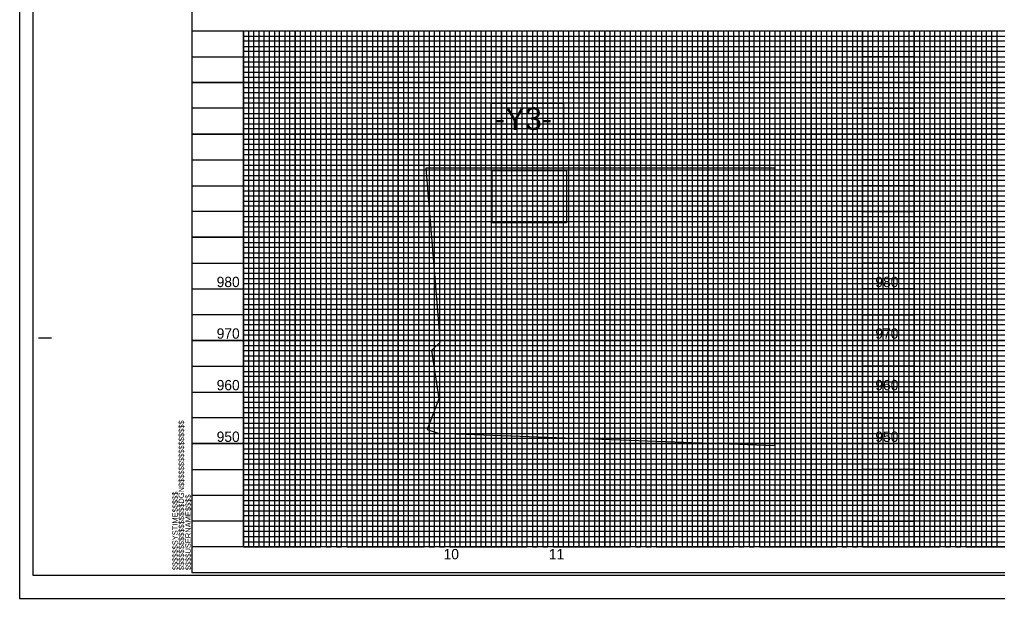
# Model space of a CAD drawing. Extents: x 1624665 to 1626605, y 896887 to 897987.
# Drawn here: x 1624665 to 1625613, y 896887 to 897448 of the extents above; entities that cross this region are included whole.
import ezdxf

# ---------------------------------------------------------------- set-up
doc = ezdxf.new("R2010")
doc.units = 0
for name, color, linetype in [('Prop DSN Text', 7, 'Continuous'), ('Prop PHM Black Shape', 7, 'Continuous'), ('Scratch_Level_1', 7, 'Continuous'), ('Sheet Cutting Line CELL', 7, 'Continuous'), ('Sheet DOT Grid CELL', 7, 'Continuous'), ('Sheet Layout Profile Border Port 2', 7, 'Continuous'), ('Sheet Plot Border Inside CELL', 7, 'Continuous'), ('Sheet Plot Border Outside CELL', 7, 'Continuous'), ('Sheet Profile CELL', 7, 'Continuous'), ('Sheet Profile Grid Major CELL', 7, 'Continuous'), ('Sheet Profile Grid Middle CELL', 7, 'Continuous'), ('Sheet Profile Grid Minor CELL', 7, 'Continuous')]:
    doc.layers.add(name, color=color, linetype=linetype)

msp = doc.modelspace()

# ---------------------------------------------------------------- linework, layer by layer
at = {"layer": 'Prop DSN Text'}
msp.add_lwpolyline([(1625122.4, 897367.44), (1625192.4, 897367.44), (1625192.4, 897337.44), (1625122.4, 897337.44)], close=True, dxfattribs=at)
at = {"layer": 'Prop PHM Black Shape'}
for points in [[(1625482.4, 897437.44), (1625532.4, 897437.44), (1625532.4, 897412.44), (1625482.4, 897412.44)], [(1625482.4, 897412.44), (1625532.4, 897412.44), (1625532.4, 897387.44), (1625482.4, 897387.44)], [(1625482.4, 897387.44), (1625532.4, 897387.44), (1625532.4, 897362.44), (1625482.4, 897362.44)], [(1625122.4, 897367.44), (1625192.4, 897367.44), (1625192.4, 897337.44), (1625122.4, 897337.44)], [(1625482.4, 897362.44), (1625532.4, 897362.44), (1625532.4, 897337.44), (1625482.4, 897337.44)], [(1625482.4, 897337.44), (1625532.4, 897337.44), (1625532.4, 897312.44), (1625482.4, 897312.44)], [(1625482.4, 897312.44), (1625532.4, 897312.44), (1625532.4, 897287.44), (1625482.4, 897287.44)], [(1625123.29, 897302.04), (1625195.25, 897302.04), (1625195.25, 897251.3), (1625123.29, 897251.3)], [(1625482.4, 897287.44), (1625532.4, 897287.44), (1625532.4, 897262.44), (1625482.4, 897262.44)], [(1625482.4, 897262.44), (1625532.4, 897262.44), (1625532.4, 897237.44), (1625482.4, 897237.44)], [(1625482.4, 897237.44), (1625532.4, 897237.44), (1625532.4, 897212.44), (1625482.4, 897212.44)], [(1625482.4, 897212.44), (1625532.4, 897212.44), (1625532.4, 897187.44), (1625482.4, 897187.44)], [(1625482.4, 897187.44), (1625532.4, 897187.44), (1625532.4, 897162.44), (1625482.4, 897162.44)], [(1625482.4, 897162.44), (1625532.4, 897162.44), (1625532.4, 897137.44), (1625482.4, 897137.44)], [(1625482.4, 897137.44), (1625532.4, 897137.44), (1625532.4, 897112.44), (1625482.4, 897112.44)], [(1625482.4, 897112.44), (1625532.4, 897112.44), (1625532.4, 897087.44), (1625482.4, 897087.44)], [(1625482.4, 897087.44), (1625532.4, 897087.44), (1625532.4, 897062.44), (1625482.4, 897062.44)], [(1625482.4, 897062.44), (1625532.4, 897062.44), (1625532.4, 897037.44), (1625482.4, 897037.44)], [(1625482.4, 897037.44), (1625532.4, 897037.44), (1625532.4, 897012.44), (1625482.4, 897012.44)], [(1625482.4, 897012.44), (1625532.4, 897012.44), (1625532.4, 896987.44), (1625482.4, 896987.44)], [(1625482.4, 896987.44), (1625532.4, 896987.44), (1625532.4, 896962.44), (1625482.4, 896962.44)], [(1625482.4, 896962.44), (1625532.4, 896962.44), (1625532.4, 896937.44), (1625482.4, 896937.44)]]:
    msp.add_lwpolyline(points, close=True, dxfattribs=at)
at = {"layer": 'Scratch_Level_1'}
msp.add_lwpolyline([(1625072.01, 897146.43), (1625072.69, 897135.35), (1625064.6, 897127.75), (1625071.58, 897080.87), (1625060.24, 897051.13), (1625071.02, 897047.47), (1625397.25, 897035.69), (1625397.25, 897304.35), (1625059.02, 897304.35)], close=True, dxfattribs=at)
at = {"layer": 'Sheet Cutting Line CELL'}
for p, q in [((1624665.4, 897987.44), (1624665.4, 896887.44)), ((1624665.4, 896887.44), (1626349.4, 896887.44))]:
    msp.add_line(p, q, dxfattribs=at)
at = {"layer": 'Sheet DOT Grid CELL'}
for p, q in [((1624832.4, 897437.44), (1626332.29, 897437.44)), ((1624882.4, 897437.44), (1624882.4, 896937.44)), ((1624932.4, 897437.44), (1624932.4, 896937.44)), ((1624982.4, 897437.44), (1624982.4, 896937.44)), ((1625032.4, 897437.44), (1625032.4, 896937.44)), ((1625082.4, 897437.44), (1625082.4, 896937.44)), ((1625132.4, 897437.44), (1625132.4, 896937.44)), ((1625182.4, 897437.44), (1625182.4, 896937.44)), ((1625232.4, 897437.44), (1625232.4, 896937.44)), ((1625282.4, 897437.44), (1625282.4, 896937.44)), ((1625332.4, 897437.44), (1625332.4, 896937.44)), ((1625382.4, 897437.44), (1625382.4, 896937.44)), ((1625432.4, 897437.44), (1625432.4, 896937.44)), ((1625482.4, 897437.44), (1625482.4, 896937.44)), ((1625532.4, 897437.44), (1625532.4, 896937.44)), ((1625582.4, 897437.44), (1625582.4, 896937.44)), ((1624832.4, 897387.44), (1626332.29, 897387.44)), ((1624832.4, 897337.44), (1626332.29, 897337.44)), ((1624832.4, 897287.44), (1626332.29, 897287.44)), ((1624832.4, 897237.44), (1626332.29, 897237.44)), ((1624832.4, 897187.44), (1626332.29, 897187.44)), ((1624832.4, 897137.44), (1626332.29, 897137.44)), ((1624832.4, 897087.44), (1626332.29, 897087.44)), ((1624832.4, 897037.44), (1626332.29, 897037.44)), ((1624832.4, 896987.44), (1626332.29, 896987.44))]:
    msp.add_line(p, q, dxfattribs=at)
at = {"layer": 'Sheet Layout Profile Border Port 2'}
msp.add_lwpolyline([(1624882.4, 897437.44), (1626282.4, 897437.44), (1626282.4, 896937.44), (1624882.4, 896937.44)], close=True, dxfattribs=at)
at = {"layer": 'Sheet Plot Border Inside CELL'}
msp.add_lwpolyline([(1624678.4, 896909.89), (1626344.9, 896909.89), (1626344.9, 897964.99), (1624678.4, 897964.99)], close=True, dxfattribs=at)
at = {"layer": 'Sheet Plot Border Outside CELL'}
msp.add_lwpolyline([(1624665.4, 896887.44), (1626349.4, 896887.44), (1626349.4, 897987.44), (1624665.4, 897987.44)], close=True, dxfattribs=at)
at = {"layer": 'Sheet Profile CELL'}
for p, q in [((1624832.4, 897437.44), (1626332.4, 897437.44)), ((1624683.9, 897139.94), (1624696.4, 897139.94)), ((1626332.4, 896937.44), (1624832.4, 896937.44)), ((1624832.4, 896912.44), (1626332.4, 896912.44)), ((1624832.4, 896912.44), (1624832.4, 896912.44)), ((1624832.4, 896912.44), (1624832.4, 896912.44)), ((1624832.4, 896912.44), (1624832.4, 896912.44)), ((1624832.4, 896912.44), (1624832.4, 896912.44)), ((1624832.4, 896912.44), (1624832.4, 896912.44)), ((1624832.4, 896912.44), (1624832.4, 896912.44)), ((1624832.4, 896912.44), (1624832.4, 896912.44))]:
    msp.add_line(p, q, dxfattribs=at)
msp.add_lwpolyline([(1626332.4, 897962.44), (1624832.4, 897962.44), (1624832.4, 896912.44), (1626332.4, 896912.44)], close=True, dxfattribs=at)
msp.add_lwpolyline([(1624869.9, 896912.44), (1624869.9, 896912.44)], dxfattribs=at)
at = {"layer": 'Sheet Profile Grid Major CELL'}
for p, q in [((1625332.4, 897437.44), (1625382.4, 897437.44)), ((1625432.4, 897437.44), (1625482.4, 897437.44)), ((1625532.4, 897437.44), (1625582.4, 897437.44)), ((1625482.4, 897412.44), (1625532.4, 897412.44)), ((1625482.4, 897387.44), (1625532.4, 897387.44)), ((1625532.4, 897362.44), (1625482.4, 897362.44)), ((1625482.4, 897337.44), (1625532.4, 897337.44)), ((1625482.4, 897312.44), (1625532.4, 897312.44)), ((1625482.4, 897287.44), (1625532.4, 897287.44)), ((1625482.4, 897262.44), (1625532.4, 897262.44)), ((1625482.4, 897237.44), (1625532.4, 897237.44)), ((1625482.4, 897212.44), (1625532.4, 897212.44)), ((1625482.4, 897187.44), (1625532.4, 897187.44)), ((1625482.4, 897162.44), (1625532.4, 897162.44)), ((1625482.4, 897137.44), (1625532.4, 897137.44)), ((1625482.4, 897112.44), (1625532.4, 897112.44)), ((1625482.4, 897087.44), (1625532.4, 897087.44)), ((1625482.4, 897062.44), (1625532.4, 897062.44)), ((1625482.4, 897037.44), (1625532.4, 897037.44)), ((1625482.4, 897012.44), (1625532.4, 897012.44)), ((1625482.4, 896987.44), (1625532.4, 896987.44)), ((1625482.4, 896962.44), (1625532.4, 896962.44)), ((1624832.4, 896937.44), (1624832.4, 896937.44))]:
    msp.add_line(p, q, dxfattribs=at)
for points in [[(1624882.4, 897437.44), (1624882.4, 896937.44), (1624932.4, 896937.44), (1624932.4, 897437.44), (1624982.4, 897437.44), (1624982.4, 896937.44), (1625032.4, 896937.44), (1625032.4, 897437.44), (1625082.4, 897437.44), (1625082.4, 896937.44), (1625132.4, 896937.44), (1625132.4, 897437.44), (1625182.4, 897437.44), (1625182.4, 896937.44), (1625232.4, 896937.44), (1625232.4, 897437.44), (1625282.4, 897437.44), (1625282.4, 896937.44), (1625332.4, 896937.44), (1625332.4, 897437.44), (1625382.4, 897437.44), (1625382.4, 896937.44), (1625432.4, 896937.44), (1625432.4, 897437.44), (1625482.4, 897437.44), (1625482.4, 896937.44), (1625532.4, 896937.44), (1625532.4, 897437.44), (1625582.4, 897437.44), (1625582.4, 896937.44), (1625632.4, 896937.44)], [(1626332.4, 897387.44), (1624832.4, 897387.44)], [(1626332.4, 897337.44), (1624832.4, 897337.44), (1624832.4, 897287.44), (1626332.4, 897287.44)], [(1626332.4, 897237.44), (1624832.4, 897237.44), (1624832.4, 897187.44), (1626332.4, 897187.44)], [(1626332.4, 897137.44), (1624832.4, 897137.44), (1624832.4, 897087.44), (1626332.4, 897087.44)], [(1626332.4, 897037.44), (1624832.4, 897037.44), (1624832.4, 897037.44), (1624832.4, 896987.44), (1626332.4, 896987.44)], [(1626332.4, 896937.44), (1624832.4, 896937.44)]]:
    msp.add_lwpolyline(points, dxfattribs=at)
at = {"layer": 'Sheet Profile Grid Middle CELL'}
for points in [[(1624857.4, 897437.44), (1624907.4, 897437.44), (1624907.4, 896937.44), (1624957.4, 896937.44), (1624957.4, 897437.44), (1625007.4, 897437.44), (1625007.4, 896937.44), (1625057.4, 896937.44), (1625057.4, 897437.44), (1625107.4, 897437.44), (1625107.4, 896937.44), (1625157.4, 896937.44), (1625157.4, 897437.44), (1625207.4, 897437.44), (1625207.4, 896937.44), (1625257.4, 896937.44), (1625257.4, 897437.44), (1625307.4, 897437.44), (1625307.4, 896937.44), (1625357.4, 896937.44), (1625357.4, 897437.44), (1625407.4, 897437.44), (1625407.4, 896937.44), (1625457.4, 896937.44), (1625457.4, 896937.44), (1625457.4, 897437.44), (1625507.4, 897437.44), (1625507.4, 896937.44), (1625557.4, 896937.44), (1625557.4, 897437.44), (1625607.4, 897437.44), (1625607.4, 896937.44), (1625657.4, 896937.44)], [(1624832.4, 897412.44), (1626332.4, 897412.44)], [(1626332.4, 897362.44), (1624832.4, 897362.44), (1624832.4, 897312.44), (1626332.4, 897312.44)], [(1626332.4, 897262.44), (1624832.4, 897262.44), (1624832.4, 897212.44), (1626332.4, 897212.44)], [(1626332.4, 897162.44), (1624832.4, 897162.44), (1624832.4, 897112.44), (1626332.4, 897112.44)], [(1626332.4, 897062.44), (1624832.4, 897062.44), (1624832.4, 897012.44), (1626332.4, 897012.44)], [(1626332.4, 896962.44), (1624832.4, 896962.44)]]:
    msp.add_lwpolyline(points, dxfattribs=at)
at = {"layer": 'Sheet Profile Grid Minor CELL'}
for p, q in [((1624882.4, 897432.44), (1626282.4, 897432.44)), ((1626282.4, 897427.44), (1624882.4, 897427.44)), ((1624882.4, 897422.44), (1626282.4, 897422.44)), ((1626282.4, 897417.44), (1624882.4, 897417.44)), ((1624882.4, 897407.44), (1626282.4, 897407.44)), ((1626282.4, 897402.44), (1624882.4, 897402.44)), ((1624882.4, 897397.44), (1626282.4, 897397.44)), ((1626282.4, 897392.44), (1624882.4, 897392.44)), ((1624882.4, 897382.44), (1626282.4, 897382.44)), ((1626282.4, 897377.44), (1624882.4, 897377.44)), ((1624882.4, 897372.44), (1626282.4, 897372.44)), ((1626282.4, 897367.44), (1624882.4, 897367.44)), ((1624882.4, 897357.44), (1626282.4, 897357.44)), ((1626282.4, 897352.44), (1624882.4, 897352.44)), ((1624882.4, 897347.44), (1626282.4, 897347.44)), ((1626282.4, 897342.44), (1624882.4, 897342.44)), ((1624882.4, 897332.44), (1626282.4, 897332.44)), ((1626282.4, 897327.44), (1624882.4, 897327.44)), ((1624882.4, 897322.44), (1626282.4, 897322.44)), ((1626282.4, 897317.44), (1624882.4, 897317.44)), ((1624882.4, 897307.44), (1626282.4, 897307.44)), ((1626282.4, 897302.44), (1624882.4, 897302.44)), ((1624882.4, 897297.44), (1626282.4, 897297.44)), ((1626282.4, 897292.44), (1624882.4, 897292.44)), ((1624882.4, 897282.44), (1626282.4, 897282.44)), ((1626282.4, 897277.44), (1624882.4, 897277.44)), ((1624882.4, 897272.44), (1626282.4, 897272.44)), ((1626282.4, 897267.44), (1624882.4, 897267.44)), ((1624882.4, 897257.44), (1626282.4, 897257.44)), ((1626282.4, 897252.44), (1624882.4, 897252.44)), ((1624882.4, 897247.44), (1626282.4, 897247.44)), ((1626282.4, 897242.44), (1624882.4, 897242.59)), ((1624882.4, 897232.44), (1626282.4, 897232.44)), ((1626282.4, 897227.44), (1624882.4, 897227.44)), ((1624882.4, 897222.44), (1626282.4, 897222.44)), ((1626282.4, 897217.44), (1624882.4, 897217.44)), ((1624882.4, 897207.44), (1626282.4, 897207.44)), ((1626282.4, 897202.44), (1624882.4, 897202.44)), ((1624882.4, 897197.44), (1626282.4, 897197.44)), ((1626282.4, 897192.44), (1624882.4, 897192.44)), ((1624882.4, 897182.44), (1626282.4, 897182.44)), ((1626282.4, 897177.44), (1624882.4, 897177.44)), ((1624882.4, 897172.44), (1626282.4, 897172.44)), ((1626282.4, 897167.44), (1624882.4, 897167.44)), ((1624882.4, 897157.44), (1626282.4, 897157.44)), ((1626282.4, 897152.44), (1624882.4, 897152.44)), ((1624882.4, 897147.44), (1626282.4, 897147.44)), ((1626282.4, 897142.44), (1624882.4, 897142.44)), ((1624882.4, 897132.44), (1626282.4, 897132.44)), ((1626282.4, 897127.44), (1624882.4, 897127.44)), ((1624882.4, 897122.44), (1626282.4, 897122.44)), ((1626282.4, 897117.44), (1624882.4, 897117.44)), ((1624882.4, 897107.44), (1626282.4, 897107.44)), ((1626282.4, 897102.44), (1624882.4, 897102.44)), ((1624882.4, 897097.44), (1626282.4, 897097.44)), ((1626282.4, 897092.44), (1624882.4, 897092.44)), ((1624882.4, 897082.44), (1626282.4, 897082.44)), ((1626282.4, 897077.44), (1624882.4, 897077.44)), ((1624882.4, 897072.44), (1626282.4, 897072.44)), ((1626282.4, 897067.44), (1624882.4, 897067.44)), ((1624882.4, 897057.44), (1626282.4, 897057.44)), ((1626282.4, 897052.44), (1624882.4, 897052.44)), ((1624882.4, 897047.44), (1626282.4, 897047.44)), ((1626282.4, 897042.44), (1624882.4, 897042.44)), ((1624882.4, 897032.44), (1626282.4, 897032.44)), ((1626282.4, 897027.44), (1624882.4, 897027.44)), ((1624882.4, 897022.44), (1626282.4, 897022.44)), ((1626282.4, 897017.44), (1624882.4, 897017.44)), ((1624882.4, 897007.44), (1626282.4, 897007.44)), ((1626282.4, 897002.44), (1624882.4, 897002.44)), ((1624882.4, 896997.44), (1626282.4, 896997.44)), ((1626282.4, 896992.44), (1624882.4, 896992.44)), ((1624882.4, 896982.44), (1626282.4, 896982.44)), ((1626282.4, 896977.44), (1624882.4, 896977.44)), ((1624882.4, 896972.44), (1626282.4, 896972.44)), ((1626282.4, 896967.44), (1624882.4, 896967.44)), ((1624882.4, 896957.44), (1626282.4, 896957.44)), ((1626282.4, 896952.44), (1624882.4, 896952.44)), ((1624882.4, 896947.44), (1626282.4, 896947.44)), ((1624882.4, 896942.44), (1626282.4, 896942.44))]:
    msp.add_line(p, q, dxfattribs=at)
for points in [[(1624882.4, 897437.44), (1624887.4, 897437.44), (1624887.4, 896937.44), (1624892.4, 896937.44), (1624892.4, 897437.44), (1624897.4, 897437.44), (1624897.4, 896937.44), (1624902.4, 896937.44), (1624902.4, 897437.44), (1624912.4, 897437.44), (1624912.4, 896937.44), (1624917.4, 896937.44), (1624917.4, 897437.44), (1624922.4, 897437.44), (1624922.4, 896937.44), (1624927.4, 896937.44), (1624937.4, 896937.44), (1624942.4, 896937.44), (1624942.4, 897437.44), (1624947.4, 897437.44), (1624947.4, 896937.44), (1624952.4, 896937.44), (1624952.4, 897437.44), (1624962.4, 897437.44), (1624962.4, 896937.44), (1624967.4, 896937.44), (1624967.4, 897437.44), (1624972.4, 897437.44), (1624972.4, 896937.44), (1624977.4, 896937.44), (1624977.4, 897437.44), (1624987.4, 897437.44), (1624987.4, 896937.44), (1624992.4, 896937.44), (1624992.4, 897437.44), (1624997.4, 897437.44), (1624997.4, 896937.44), (1625002.4, 896937.44), (1625002.4, 897437.44), (1625012.4, 897437.44), (1625012.4, 896937.44), (1625017.4, 896937.44), (1625017.4, 897437.44), (1625022.4, 897437.44), (1625022.4, 896937.44), (1625027.4, 896937.44), (1625027.4, 897437.44), (1625037.4, 897437.44), (1625037.4, 896937.44), (1625042.4, 896937.44), (1625042.4, 897437.44), (1625047.4, 897437.44), (1625047.4, 896937.44), (1625052.4, 896937.44), (1625052.4, 897437.44), (1625062.4, 897437.44), (1625062.4, 896937.44), (1625067.4, 896937.44), (1625067.4, 897437.44), (1625072.4, 897437.44), (1625072.4, 896937.44), (1625077.4, 896937.44), (1625077.4, 897437.44), (1625087.4, 897437.44), (1625087.4, 896937.44), (1625092.4, 896937.44), (1625092.4, 897437.44), (1625097.4, 897437.44), (1625097.4, 896937.44)], [(1624927.4, 896937.44), (1624927.4, 897437.44), (1624937.4, 897437.44), (1624937.4, 896937.44)], [(1625097.4, 896937.44), (1625102.4, 896937.44), (1625102.4, 897437.44), (1625112.4, 897437.44), (1625112.4, 896937.44), (1625117.4, 896937.44), (1625117.4, 897437.44), (1625122.4, 897437.44), (1625122.4, 896937.44), (1625127.4, 896937.44), (1625127.4, 897437.44), (1625137.4, 897437.44), (1625137.4, 896937.44), (1625142.4, 896937.44), (1625142.4, 897437.44), (1625147.4, 897437.44), (1625147.4, 896937.44), (1625152.4, 896937.44), (1625152.4, 897437.44), (1625162.4, 897437.44), (1625162.4, 896937.44), (1625167.4, 896937.44), (1625167.4, 897437.44), (1625172.4, 897437.44), (1625172.4, 896937.44), (1625177.4, 896937.44), (1625177.4, 897437.44), (1625187.4, 897437.44), (1625187.4, 896937.44), (1625192.4, 896937.44), (1625192.4, 897437.44), (1625197.4, 897437.44), (1625197.4, 896937.44), (1625202.4, 896937.44), (1625202.4, 897437.44), (1625212.4, 897437.44), (1625212.4, 896937.44), (1625217.4, 896937.44), (1625217.4, 897437.44), (1625222.4, 897437.44), (1625222.4, 896937.44), (1625227.4, 896937.44), (1625227.4, 897437.44), (1625237.4, 897437.44), (1625237.4, 896937.44), (1625242.4, 896937.44), (1625242.4, 897437.44), (1625247.4, 897437.44), (1625247.4, 896937.44), (1625252.4, 896937.44), (1625252.4, 897437.44), (1625262.4, 897437.44), (1625262.4, 896937.44), (1625267.4, 896937.44), (1625267.4, 897437.44), (1625272.4, 897437.44), (1625272.4, 896937.44), (1625277.4, 896937.44), (1625277.4, 897437.44), (1625287.4, 897437.44), (1625287.4, 896937.44), (1625292.4, 896937.44), (1625292.4, 897437.44), (1625297.4, 897437.44), (1625297.4, 896937.44), (1625302.4, 896937.44), (1625302.4, 897437.44), (1625312.4, 897437.44), (1625312.4, 896937.44), (1625317.4, 896937.44), (1625317.4, 897437.44), (1625322.4, 897437.44), (1625322.4, 896937.44), (1625327.4, 896937.44), (1625327.4, 897437.44), (1625337.4, 897437.44), (1625337.4, 896937.44), (1625342.4, 896937.44), (1625342.4, 897437.44), (1625347.4, 897437.44), (1625347.4, 896937.44), (1625352.4, 896937.44), (1625352.4, 897437.44), (1625362.4, 897437.44), (1625362.4, 896937.44), (1625367.4, 896937.44), (1625367.4, 897437.44), (1625372.4, 897437.44), (1625372.4, 896937.44), (1625377.4, 896937.44), (1625377.4, 897437.44), (1625387.4, 897437.44), (1625387.4, 896937.44), (1625392.4, 896937.44), (1625392.4, 897437.44), (1625397.4, 897437.44), (1625397.4, 896937.44), (1625402.4, 896937.44), (1625402.4, 897437.44), (1625412.4, 897437.44)], [(1625412.4, 897437.44), (1625412.4, 896937.44), (1625417.4, 896937.44), (1625417.4, 897437.44), (1625422.4, 897437.44), (1625422.4, 896937.44), (1625427.4, 896937.44), (1625427.4, 897437.44), (1625437.4, 897437.44), (1625437.4, 896937.44), (1625442.4, 896937.44), (1625442.4, 897437.44), (1625447.4, 897437.44), (1625447.4, 896937.44), (1625452.4, 896937.44), (1625452.4, 897437.44), (1625462.4, 897437.44), (1625462.4, 896937.44), (1625467.4, 896937.44), (1625467.4, 897437.44), (1625472.4, 897437.44), (1625472.4, 896937.44), (1625477.4, 896937.44), (1625477.4, 897437.44), (1625487.4, 897437.44), (1625487.4, 896937.44), (1625492.4, 896937.44), (1625492.4, 897437.44), (1625497.4, 897437.44), (1625497.4, 896937.44), (1625502.4, 896937.44), (1625502.4, 897437.44), (1625512.4, 897437.44), (1625512.4, 896937.44), (1625517.4, 896937.44), (1625517.4, 897437.44), (1625522.4, 897437.44), (1625522.4, 896937.44), (1625527.4, 896937.44), (1625527.4, 897437.44), (1625537.4, 897437.44), (1625537.4, 896937.44), (1625537.4, 896937.44), (1625542.4, 896937.44), (1625542.4, 897437.44), (1625547.4, 897437.44), (1625547.4, 896937.44), (1625552.4, 896937.44), (1625552.4, 897437.44), (1625562.4, 897437.44), (1625562.4, 896937.44), (1625567.4, 896937.44), (1625567.4, 897437.44), (1625572.4, 897437.44), (1625572.4, 896937.44), (1625577.4, 896937.44), (1625577.4, 897437.44), (1625587.4, 897437.44), (1625587.4, 896937.44), (1625592.4, 896937.44), (1625592.4, 897437.44), (1625597.4, 897437.44), (1625597.4, 896937.44), (1625602.4, 896937.44), (1625602.4, 897437.44), (1625612.4, 897437.44), (1625612.4, 896937.44), (1625617.4, 896937.44)]]:
    msp.add_lwpolyline(points, dxfattribs=at)

# ---------------------------------------------------------------- texts
at = {"layer": 'Prop DSN Text'}
for s, height, p in [('-Y3-', 21.875, (1625125.95, 897341.5)), ('980', 10, (1624856.41, 897189.17)), ('980', 10, (1625494.68, 897189.17)), ('970', 10, (1624856.41, 897139.17)), ('970', 10, (1625494.68, 897139.17)), ('960', 10, (1624856.41, 897089.17)), ('960', 10, (1625494.68, 897089.17)), ('950', 10, (1624856.41, 897039.17)), ('950', 10, (1625494.68, 897039.17)), ('10', 10, (1625076.31, 896925.38)), ('11', 10, (1625178.28, 896925.38))]:
    msp.add_text(s, height=height, dxfattribs=at).set_placement(p)
at = {"layer": 'Sheet Profile CELL'}
for s, p in [('$$$$$$$$$$$$$$$$DGN$$$$$$$$$$$$$$$$', (1624824.76, 896914.82)), ('$$$$$$SYSTIME$$$$$', (1624818.71, 896914.82)), ('$$$$USERNAME$$$$', (1624831.34, 896914.83))]:
    msp.add_text(s, height=5.25, rotation=90, dxfattribs=at).set_placement(p)

doc.saveas('drawing.dxf')
